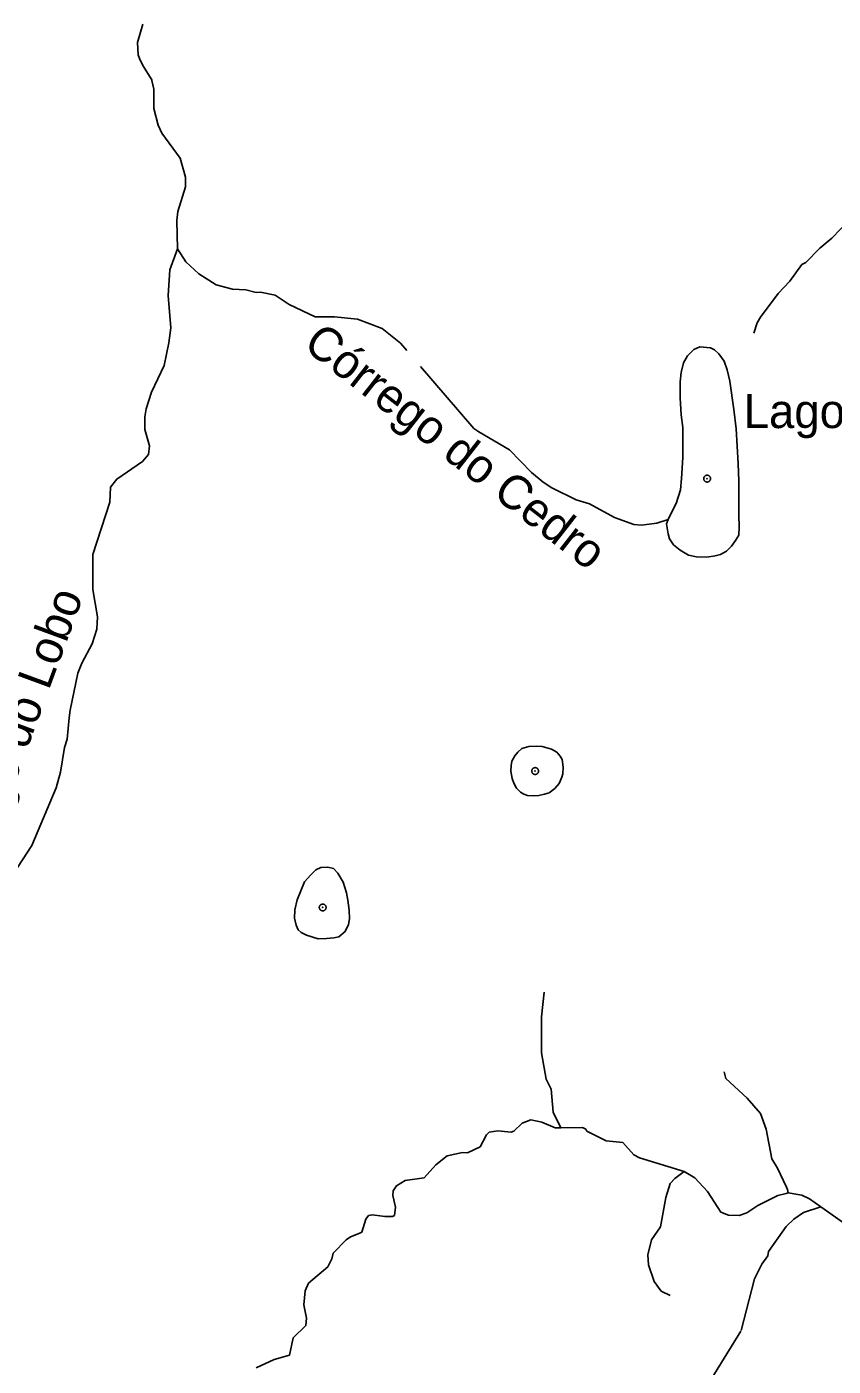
# Model space of a CAD drawing. Extents: x 393 to 446.6, y 8175.5 to 8231.
# Drawn here: x 404.19 to 407.98, y 8190.87 to 8197.16 of the extents above; entities that cross this region are included whole.
import ezdxf
from ezdxf.enums import TextEntityAlignment as Align

# ---------------------------------------------------------------- set-up
doc = ezdxf.new("R2010")
doc.units = 0
doc.header["$LTSCALE"] = 0.064
doc.header["$PDMODE"] = 32
doc.header["$PDSIZE"] = 0.032
doc.linetypes.add('LONG_DASHED', pattern=[7.5, 6, -1.5])
for name, color, linetype, lineweight in [('3', 7, 'LONG_DASHED', 25), ('7', 7, 'Continuous', 25), ('9', 7, 'LONG_DASHED', 25)]:
    doc.layers.add(name, color=color, linetype=linetype, lineweight=lineweight)
doc.layers.add('61', color=7, linetype='Continuous')

msp = doc.modelspace()

# ---------------------------------------------------------------- linework, layer by layer
at = {"layer": '3'}
for points in [[(407.2001, 8194.8482), (407.2208, 8194.8896), (407.2373, 8194.9227), (407.258, 8194.9869), (407.2621, 8195.0406), (407.2683, 8195.14), (407.2683, 8195.2186), (407.2683, 8195.2806), (407.2601, 8195.3406), (407.2559, 8195.4192), (407.2559, 8195.4958), (407.2601, 8195.5392), (407.2725, 8195.5848), (407.2911, 8195.6179), (407.3201, 8195.6468), (407.349, 8195.6592), (407.3987, 8195.6551), (407.4173, 8195.6448), (407.438, 8195.6261), (407.4628, 8195.593), (407.4773, 8195.5517), (407.4897, 8195.4979), (407.5083, 8195.3655), (407.5187, 8195.2744), (407.529, 8195.111), (407.5311, 8195.0282), (407.5311, 8194.9413), (407.5311, 8194.8689), (407.5332, 8194.8131), (407.5311, 8194.7738), (407.5166, 8194.7489), (407.498, 8194.722), (407.4732, 8194.6993), (407.4463, 8194.6827), (407.4214, 8194.6765), (407.3821, 8194.6703), (407.3325, 8194.6724), (407.2952, 8194.6807), (407.2559, 8194.7034), (407.2249, 8194.7282), (407.2063, 8194.7572), (407.2001, 8194.78), (407.1959, 8194.7986), (407.1918, 8194.8276)], [(406.4874, 8193.5855), (406.5064, 8193.5664), (406.5213, 8193.5569), (406.5382, 8193.5505), (406.5647, 8193.5484), (406.5912, 8193.5495), (406.6187, 8193.5558), (406.6399, 8193.5632), (406.6674, 8193.5833), (406.6875, 8193.6066), (406.7002, 8193.6363), (406.7045, 8193.6522), (406.7066, 8193.684), (406.7013, 8193.7189), (406.6928, 8193.7348), (406.6769, 8193.7539), (406.6515, 8193.7687), (406.6081, 8193.7803), (406.5795, 8193.7825), (406.5456, 8193.7803), (406.5117, 8193.7708), (406.4927, 8193.7539), (406.4789, 8193.7369), (406.4651, 8193.7115), (406.462, 8193.6914), (406.4598, 8193.6649), (406.4662, 8193.6299), (406.4747, 8193.6077)], [(405.5004, 8192.8942), (405.4753, 8192.9068), (405.4616, 8192.9182), (405.4513, 8192.9399), (405.4444, 8192.9742), (405.4455, 8193.0131), (405.4558, 8193.06), (405.4913, 8193.1447), (405.5199, 8193.1778), (405.5439, 8193.2007), (405.5679, 8193.211), (405.6, 8193.2133), (405.6263, 8193.2076), (405.648, 8193.1858), (405.672, 8193.1424), (405.688, 8193.0921), (405.6937, 8193.0577), (405.7006, 8193.0108), (405.7029, 8192.9708), (405.6972, 8192.9445), (405.6823, 8192.9102), (405.6514, 8192.8862), (405.6286, 8192.8816), (405.5942, 8192.8782), (405.5553, 8192.877)]]:
    msp.add_lwpolyline(points, close=True, dxfattribs=at)
for p in [(407.3828, 8195.0399), (406.5746, 8193.6652), (405.5762, 8193.0238)]:
    msp.add_point(p, dxfattribs=at)
at = {"layer": '7'}
for points in [[(404.894, 8196.1205), (404.8909, 8196.2535), (404.8957, 8196.2954), (404.9313, 8196.4117), (404.9313, 8196.4569), (404.907, 8196.5473), (404.8198, 8196.6636), (404.8037, 8196.7024), (404.7827, 8196.7799), (404.7827, 8196.8703), (404.7738, 8196.9119), (404.773, 8196.9155), (404.731, 8196.9817), (404.716, 8197.015), (404.7084, 8197.0318), (404.7052, 8197.0899), (404.731, 8197.1771)], [(407.603, 8195.7246), (407.6183, 8195.7722), (407.6344, 8195.7997), (407.7168, 8195.9111), (407.7717, 8195.9676), (407.8282, 8196.0467), (407.846, 8196.0564), (407.9122, 8196.1242), (407.9687, 8196.1711), (408.0963, 8196.3019), (408.2012, 8196.3761), (408.2642, 8196.4068), (408.3646, 8196.4273)], [(404.0528, 8193.0771), (404.2094, 8193.3145), (404.3241, 8193.5858), (404.3435, 8193.6601), (404.3629, 8193.7764), (404.3758, 8193.8151), (404.3853, 8193.9149), (404.3887, 8193.9508), (404.4258, 8194.1252), (404.4436, 8194.172), (404.4936, 8194.264), (404.5146, 8194.3318), (404.5179, 8194.39), (404.4953, 8194.5192), (404.4953, 8194.6839), (404.576, 8194.9293), (404.5792, 8195.0004), (404.6083, 8195.0375), (404.7294, 8195.1198), (404.7569, 8195.1538), (404.7617, 8195.1941), (404.7407, 8195.2717), (404.7407, 8195.3298), (404.7472, 8195.3685), (404.7714, 8195.4461), (404.8311, 8195.572), (404.8538, 8195.6786), (404.8618, 8195.7496), (404.8505, 8195.9014), (404.8586, 8196.0209), (404.894, 8196.1205)]]:
    msp.add_lwpolyline(points, dxfattribs=at)
at = {"layer": '9'}
for points in [[(407.2001, 8194.8482), (407.1461, 8194.83), (407.0749, 8194.8218), (407.0386, 8194.8243), (406.9482, 8194.8566), (406.8303, 8194.9212), (406.7679, 8194.9404), (406.7673, 8194.9406), (406.6527, 8194.9971), (406.6122, 8195.0229), (406.5574, 8195.0682), (406.454, 8195.1747), (406.3099, 8195.2607), (406.2861, 8195.2749), (405.9422, 8195.677), (405.855, 8195.7464), (405.7403, 8195.79), (405.6321, 8195.8013), (405.5401, 8195.8013), (405.419, 8195.8594), (405.3527, 8195.903), (405.2833, 8195.9159), (405.2639, 8195.9143), (405.2155, 8195.9272), (405.1525, 8195.9305), (405.075, 8195.9515), (404.9936, 8196.0028), (404.9329, 8196.0588), (404.894, 8196.1205)], [(406.6171, 8192.6263), (406.6042, 8192.5104), (406.6042, 8192.3408), (406.6268, 8192.2165), (406.6494, 8192.1696), (406.6591, 8192.0614), (406.6958, 8191.9874)], [(407.4628, 8192.2517), (407.4713, 8192.2197), (407.5715, 8192.1276), (407.6344, 8192.055), (407.6603, 8191.9823), (407.6877, 8191.8418), (407.7136, 8191.7982), (407.7555, 8191.7087), (407.7604, 8191.6981), (407.7631, 8191.6815)], [(405.2639, 8190.86), (405.3479, 8190.8988), (405.4205, 8190.9197), (405.4367, 8191.0005), (405.4964, 8191.0586), (405.4997, 8191.0926), (405.4868, 8191.1555), (405.4932, 8191.2217), (405.5094, 8191.2573), (405.5998, 8191.3348), (405.6192, 8191.3719), (405.6257, 8191.3978), (405.687, 8191.4607), (405.7064, 8191.4752), (405.7437, 8191.4889), (405.7596, 8191.4974), (405.7785, 8191.558), (405.7909, 8191.5753), (405.8097, 8191.5786), (405.8679, 8191.5705), (405.905, 8191.5705), (405.9138, 8191.5757), (405.9184, 8191.6142), (405.9056, 8191.6691), (405.9079, 8191.6924), (405.9228, 8191.7159), (405.9631, 8191.7401), (406.0536, 8191.753), (406.1085, 8191.8144), (406.1618, 8191.8563), (406.2328, 8191.8725), (406.257, 8191.8709), (406.3167, 8191.8983), (406.3458, 8191.9548), (406.3587, 8191.9677), (406.3991, 8191.9742), (406.4621, 8191.9677), (406.475, 8191.9726), (406.5138, 8192.0097), (406.5541, 8192.0259), (406.6058, 8192.0146), (406.6688, 8191.9871), (406.6958, 8191.9874)], [(406.6958, 8191.9874), (406.7964, 8191.9887), (406.8125, 8191.9823), (406.8174, 8191.9726), (406.9078, 8191.9274), (406.9869, 8191.9193), (407.0377, 8191.8604), (407.0657, 8191.8464), (407.2753, 8191.782)], [(407.2089, 8191.199), (407.1662, 8191.2201), (407.1339, 8191.2653), (407.108, 8191.3445), (407.1048, 8191.3913), (407.1209, 8191.4607), (407.1645, 8191.5221), (407.1887, 8191.661), (407.2097, 8191.7256), (407.2308, 8191.7497), (407.2753, 8191.782)], [(407.2753, 8191.782), (407.3255, 8191.7528), (407.3841, 8191.6884), (407.4326, 8191.6125), (407.4471, 8191.5921), (407.4829, 8191.5769), (407.534, 8191.575), (407.5702, 8191.5878), (407.6215, 8191.6222), (407.7152, 8191.669), (407.7549, 8191.6794), (407.7631, 8191.6815)], [(407.7631, 8191.6815), (407.8273, 8191.671), (407.8647, 8191.6535), (407.9175, 8191.6163)], [(407.3389, 8190.705), (407.5424, 8191.0344), (407.6054, 8191.2783), (407.6393, 8191.3461), (407.6683, 8191.3865), (407.6716, 8191.4058), (407.7548, 8191.5243), (407.7555, 8191.5253), (407.7911, 8191.5592), (407.8363, 8191.5899), (407.9172, 8191.6162), (407.9175, 8191.6163)], [(407.9175, 8191.6163), (408.0398, 8191.5302), (408.1092, 8191.5172), (408.148, 8191.514), (408.2045, 8191.5221), (408.2755, 8191.5511), (408.3821, 8191.5835), (408.413, 8191.5806), (408.4694, 8191.5545)]]:
    msp.add_lwpolyline(points, dxfattribs=at)

# ---------------------------------------------------------------- texts
at = {"layer": '61'}
for s, rotation, p in [('Córrego do Cedro', 322.001, (406.1528, 8195.1301)), ('Córrego do Lobo', 69.808, (404.1756, 8193.7341))]:
    msp.add_text(s, height=0.16, rotation=rotation, dxfattribs=at).set_placement(p, align=Align.CENTER)
msp.add_text('Lagoa do Cervo', height=0.16, dxfattribs=at).set_placement((407.5548, 8195.2777))

doc.saveas('drawing.dxf')
